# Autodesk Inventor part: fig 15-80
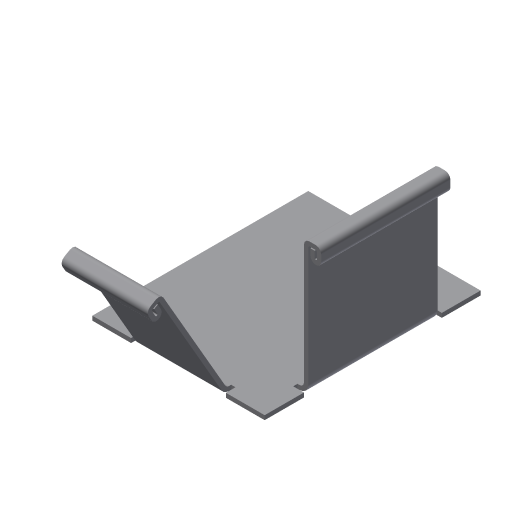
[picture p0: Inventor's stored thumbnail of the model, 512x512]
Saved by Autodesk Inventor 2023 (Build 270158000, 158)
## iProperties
Created: 2002-04
Part Number: fig 15-80
Document SubType Name: Sheet Metal
Density: 1 g/cm^3
Sheet Metal Rule: Default
Material: Generic
Appearance: Default
Control State: 0
Master: False
Checked Out: False
Shininess: 77.0
Angle Display Precision: 2
Document Length Units: 11269
Document Angle Units: 11279
Document Time Units: 11290
Document Mass Units: 11283
Document Length Units Precision: 3
Document Angle Units Precision: 2
Compacted: True
Density: 0.0
Volumn: 0.0
Area: 0.0
PropertySet Name: Model Information
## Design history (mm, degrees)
node "Face1"
  sketch "Sketch1"
    geometry: L1 (-17.882, 11.882)-(2.118, 11.882); L2 (2.118, 11.882)-(2.118, -13.176); L3 (2.118, -13.176)-(-17.882, -13.176); L4 (-17.882, -13.176)-(-17.882, 11.882)
    constraints: 8 end point, 2 parallel, 1 horizontal, 1 perpendicular
    dimensions: "d17" = 20 distance of L2.end L3.end
node "Flange2"
node "Flange3"
feature "Hem8" dims "d82" = 0.5 (= BendReliefWidth), "d83" = 0.25 (= BendReliefDepth), "d84" = 1 (= MinimumRemnant), "d85" = 0.5 (= BendRadius), "d108" = 2 (= 4 x Thickness), "d109" = 0.25 (= 0.5 x Thickness), "d110" = 0.125 (= 0.5 x d109), "d114" = 0.5 (= Thickness), "SeamGap" = 0.01
feature "Hem9" dims "d89" = 0.5 (= BendReliefWidth), "d90" = 0.25 (= BendReliefDepth), "d91" = 1 (= MinimumRemnant), "d92" = 0.5 (= BendRadius), "d111" = 2 (= 4 x Thickness), "d112" = 0.25 (= 0.5 x Thickness), "d113" = 0.125 (= 0.5 x d112), "d114" = 0.5 (= Thickness), "SeamGap" = 0.01
body "Solid1"
face "Plate1" dims "d114" = 0.5 (= Thickness)
sketch "Sketch3"
  geometry: L1 (5, 0)-(20, 0); L2 (20, 0)-(20, 15); L3 (20, 15)-(5, 15); L4 (5, 15)-(5, 0)
  constraints: 8 end point
face "Plate3" dims "d6" = 15, "d7" = 90 deg, "d8" = 0.5 (= BendRadius), "d18" = 5, "d19" = 15, "d114" = 0.5 (= Thickness), "MinimumRemnant" = 1 (= 2 x Thickness), "BendReliefWidth" = 0.5 (= Thickness)
bend "Bend2" dims "d6" = 15, "d7" = 90 deg, "d8" = 0.5 (= BendRadius), "d56" = 0.5 (= BendReliefWidth), "d57" = 0.25 (= BendReliefDepth), "d58" = 1 (= MinimumRemnant), "d114" = 0.5 (= Thickness), "SeamGap" = 0.01, "MinimumRemnant" = 1 (= 2 x Thickness), "BendReliefWidth" = 0.5 (= Thickness), "TransitionRadius" = 0.5 (= BendRadius)
sketch "Sketch6"
  geometry: L1 (15, 0)-(5, 0); L2 (5, 0)-(5, 15); L3 (5, 15)-(15, 15); L4 (15, 15)-(15, 0)
  constraints: 8 end point
face "Plate4" dims "d20" = 5, "d21" = 10, "d23" = 15, "d24" = 60 deg, "d25" = 0.5 (= BendRadius), "d114" = 0.5 (= Thickness), "MinimumRemnant" = 1 (= 2 x Thickness), "BendReliefWidth" = 0.5 (= Thickness)
bend "Bend3" dims "d22" = 0.5 (= BendRadius), "d23" = 15, "d24" = 60 deg, "d25" = 0.5 (= BendRadius), "d59" = 0.5 (= BendReliefWidth), "d60" = 0.25 (= BendReliefDepth), "d61" = 1 (= MinimumRemnant), "d114" = 0.5 (= Thickness), "SeamGap" = 0.01, "MinimumRemnant" = 1 (= 2 x Thickness), "BendReliefWidth" = 0.5 (= Thickness)
sketch "Sketch12"
  geometry: L1 (0.433, 0.25)-(0, 0); L2 (-0.171, 0.046)-(-0.82, -0.329); L3 (-0.866, -0.5)-(-0.491, -1.15); L4 (-0.275, -1.025)-(-0.65, -0.375); L5 (-0.65, -0.375)-(-0.217, -0.125); L6 (-0.217, -0.125)-(0.158, -0.775); L7 (-0.924, -1.4)-(-1.299, -0.75); L8 (-1.07, 0.104)-(-0.421, 0.479); A1 r 0.125 centre (-0.108, -0.063) between (0, 0) and (-0.171, 0.046); A2 r 0.125 centre (-0.758, -0.438) between (-0.82, -0.329) and (-0.866, -0.5); A3 r 0.125 centre (-0.383, -1.087) between (-0.491, -1.15) and (-0.275, -1.025); A4 r 0.625 centre (-0.383, -1.087) between (-0.924, -1.4) and (0.158, -0.775); A5 r 0.625 centre (-0.758, -0.438) between (-1.07, 0.104) and (-1.299, -0.75); A6 r 0.625 centre (-0.108, -0.063) between (0.433, 0.25) and (-0.421, 0.479); 2 further points
  constraints: 16 end point, 12 point on circle
sketch "Sketch13"
  geometry: L1 (0.5, 0)-(0, 0); L2 (-0.125, 0.125)-(-0.875, 0.125); L3 (-1, 0)-(-1, -0.75); L4 (-0.75, -0.75)-(-0.75, 0); L5 (-0.75, 0)-(-0.25, 0); L6 (-0.25, 0)-(-0.25, -0.75); L7 (-1.5, -0.75)-(-1.5, 0); L8 (-0.875, 0.625)-(-0.125, 0.625); A1 r 0.125 centre (-0.125, 0) between (0, 0) and (-0.125, 0.125); A2 r 0.125 centre (-0.875, 0) between (-0.875, 0.125) and (-1, 0); A3 r 0.125 centre (-0.875, -0.75) between (-1, -0.75) and (-0.75, -0.75); A4 r 0.625 centre (-0.875, -0.75) between (-1.5, -0.75) and (-0.25, -0.75); A5 r 0.625 centre (-0.875, 0) between (-0.875, 0.625) and (-1.5, 0); A6 r 0.625 centre (-0.125, 0) between (0.5, 0) and (-0.125, 0.625); 2 further points
  constraints: 16 end point, 12 point on circle
other parameters: "Thickness" = 0.5, "BendRadius" = 0.5 (= Thickness), "BendReliefDepth" = 0.25 (= 0.5 x Thickness), "CornerReliefSize" = 2 (= 4 x Thickness), "d0" = 0.5 (= BendRadius), "d5" = 0.5 (= BendRadius), "d26" = 0.5 (= BendRadius), "d30" = 0.5 (= BendRadius), "JacobiRadiusSize" = 0.5 (= Thickness), "GapSize" = 0.5 (= Thickness)
